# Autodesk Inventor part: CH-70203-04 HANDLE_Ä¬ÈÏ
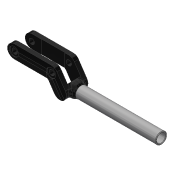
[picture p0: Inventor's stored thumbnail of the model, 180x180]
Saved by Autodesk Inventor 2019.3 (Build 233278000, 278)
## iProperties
Created: 2010-06
Part Number: CH-70203-04 HANDLE_Ä¬ÈÏ
Material: Ogólny
Document SubType Name: Modeling
Designer: CADENGINEERING4
Density: 1 g/cm^3
Appearance: Gładki — czarny
Author: CADENGINEERING4
Revision Number: ÈÎºÎ
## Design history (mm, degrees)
feature "NONE"
node "Bryła1"
